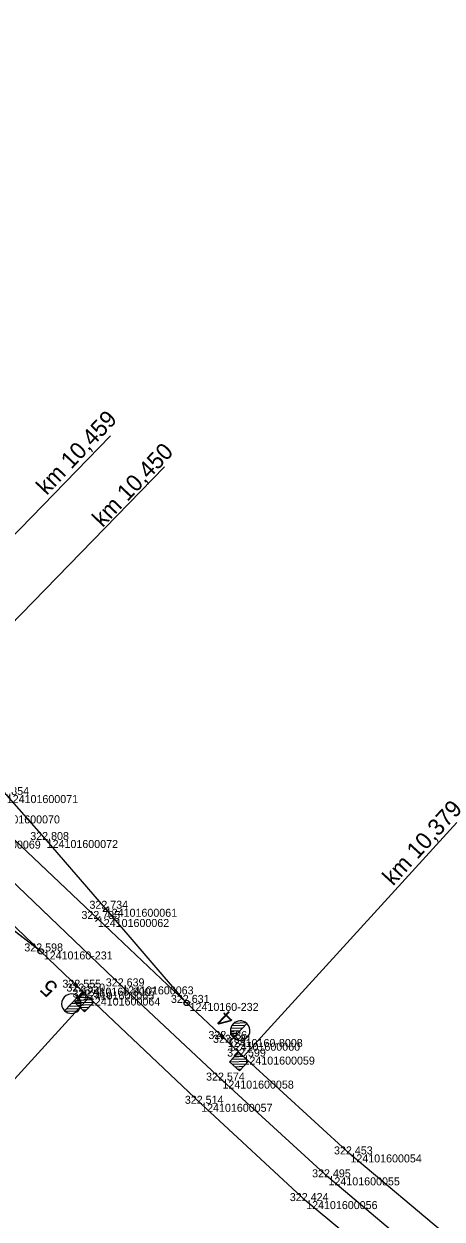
# Model space of a CAD drawing. Extents: x -616949 to -607976, y -1164436 to -1159224.
# Drawn here: x -616226.9 to -616164.1, y -1159749.3 to -1159570.1 of the extents above; entities that cross this region are included whole.
import ezdxf

# ---------------------------------------------------------------- set-up
doc = ezdxf.new("R2010")
doc.units = 0
for name, color, linetype in [('Vrstva 1', 7, 'Continuous'), ('Vrstva 2', 7, 'Continuous'), ('Vrstva 3', 7, 'Continuous'), ('Vrstva 60', 7, 'Continuous'), ('Vrstva 61', 7, 'Continuous')]:
    doc.layers.add(name, color=color, linetype=linetype)

msp = doc.modelspace()

# ---------------------------------------------------------------- linework, layer by layer
at = {"layer": 'Vrstva 1'}
for points in [[(-616196.14, -1159722.89), (-616196.73, -1159722.32), (-616202.46, -1159716.91), (-616215.79, -1159704.32), (-616232.19, -1159688.78), (-616245.9, -1159675.68), (-616250.85, -1159670.95), (-616252.01, -1159669.85), (-616262.33, -1159660.01), (-616274.66, -1159648.21), (-616291.39, -1159632.22), (-616312.18, -1159612.35), (-616313.6, -1159610.97), (-616321.94, -1159603.01), (-616323.38, -1159601.63), (-616330.7, -1159594.64), (-616332.15, -1159593.27), (-616353.46, -1159572.9), (-616354.89, -1159571.54), (-616372.69, -1159554.54)], [(-616218.05, -1159715.21), (-616218.66, -1159714.63), (-616224.36, -1159709.19), (-616237.66, -1159696.51), (-616252.73, -1159682.15), (-616263.69, -1159671.68), (-616264.9, -1159670.55), (-616281.06, -1159655.11), (-616297.26, -1159639.59), (-616319.41, -1159618.4), (-616337.57, -1159601.02), (-616360.84, -1159578.72), (-616379.28, -1159561.06)], [(-616196.14, -1159722.89), (-616196.73, -1159722.32), (-616202.46, -1159716.91), (-616214.6, -1159702.79), (-616223.47, -1159692.48), (-616229.46, -1159685.74), (-616241.59, -1159673.27), (-616259.02, -1159656.6), (-616271.36, -1159644.82), (-616287.75, -1159629.14), (-616308.99, -1159608.84), (-616310.74, -1159607.16), (-616318.53, -1159599.72), (-616320.21, -1159598.1), (-616327.35, -1159591.27), (-616329.08, -1159589.6), (-616351, -1159568.64)], [(-616166.13, -1159755.81), (-616181.17, -1159743.07), (-616197.09, -1159728.56), (-616212.13, -1159714.43), (-616235.07, -1159692.57), (-616248.23, -1159679.98), (-616265.42, -1159663.57), (-616277.85, -1159651.72), (-616294.35, -1159635.93), (-616315.47, -1159615.78), (-616316.9, -1159614.42), (-616325.14, -1159606.55), (-616326.55, -1159605.19), (-616333.88, -1159598.19), (-616335.34, -1159596.8), (-616356.93, -1159576.13)], [(-616218.05, -1159715.21), (-616218.66, -1159714.63), (-616224.36, -1159709.19), (-616239.15, -1159697.79)], [(-615908.84, -1159889.93), (-615910.27, -1159889.25), (-615923.84, -1159882.78), (-615939.55, -1159877.3), (-615950.02, -1159873.65), (-615958.35, -1159870.6), (-615972.88, -1159864.59), (-615984.54, -1159859.14), (-616001.22, -1159851.17), (-616023, -1159840.76), (-616044.09, -1159830.68), (-616066.72, -1159819.87), (-616088.67, -1159809.39), (-616107.11, -1159800.11), (-616112.99, -1159796.93), (-616128.47, -1159787.95), (-616137.63, -1159782.18), (-616142.77, -1159778.79), (-616153.3, -1159771.43), (-616169.07, -1159759.51), (-616184.52, -1159746.63), (-616200.28, -1159732.04), (-616217.13, -1159716.1), (-616218.05, -1159715.21)], [(-615938.86, -1159875.61), (-615940.27, -1159874.93), (-615953.84, -1159868.46), (-615968.03, -1159859.68), (-615983.58, -1159849.96), (-615996.64, -1159842.51), (-616003.45, -1159838.94), (-616018.15, -1159831.94), (-616039.7, -1159822.03), (-616063.66, -1159811.08), (-616084.21, -1159801.41), (-616107.46, -1159789.34), (-616114.32, -1159785.46), (-616128.35, -1159776.94), (-616131.48, -1159774.93), (-616137.2, -1159771.16), (-616148.09, -1159763.54), (-616163.09, -1159752.06), (-616177.88, -1159739.63), (-616193.93, -1159724.96), (-616196.14, -1159722.89)]]:
    msp.add_lwpolyline(points, dxfattribs=at)
at = {"layer": 'Vrstva 2'}
for p, q in [((-616224.36, -1159709.19), (-616239.15, -1159697.79)), ((-616214.21, -1159702.48), (-616214.99, -1159703.1)), ((-616215.45, -1159703.95), (-616216.13, -1159704.68)), ((-616202.46, -1159716.91), (-616214.6, -1159702.79)), ((-616218.76, -1159715.97), (-616220.78, -1159718.09)), ((-616218.36, -1159716.64), (-616219.42, -1159716.67)), ((-616218.53, -1159716.26), (-616219.05, -1159716.28)), ((-616218.76, -1159715.97), (-616218.05, -1159715.21)), ((-616218.85, -1159718.17), (-616220.62, -1159718.22)), ((-616218.51, -1159717.78), (-616220.53, -1159717.84)), ((-616218.35, -1159717.4), (-616220.16, -1159717.45)), ((-616218.31, -1159717.02), (-616219.79, -1159717.06)), ((-616195.68, -1159720.32), (-616193.67, -1159720.26)), ((-616195.43, -1159722.13), (-616193.42, -1159720)), ((-616195.35, -1159719.93), (-616193.58, -1159719.87)), ((-616195.43, -1159722.13), (-616196.14, -1159722.89)), ((-616195.88, -1159721.08), (-616194.4, -1159721.04)), ((-616195.84, -1159720.7), (-616194.03, -1159720.65)), ((-616195.83, -1159721.46), (-616194.77, -1159721.43)), ((-616195.66, -1159721.84), (-616195.14, -1159721.82))]:
    msp.add_line(p, q, dxfattribs=at)
for points in [[(-616218.05, -1159715.21), (-616218.66, -1159714.63), (-616224.36, -1159709.19), (-616237.66, -1159696.51)], [(-616196.14, -1159722.89), (-616196.73, -1159722.32), (-616202.46, -1159716.91), (-616215.79, -1159704.32)], [(-616219.54, -1159714.15), (-616218.66, -1159714.63), (-616219.18, -1159713.78)], [(-616197.61, -1159721.85), (-616196.73, -1159722.32), (-616197.26, -1159721.47)]]:
    msp.add_lwpolyline(points, dxfattribs=at)
for centre in [(-616224.36, -1159709.19), (-616202.46, -1159716.91)]:
    msp.add_circle(centre, 0.4, dxfattribs=at)
for centre, start, end in [((-616219.77, -1159717.03), 46.3462, 226.8158), ((-616219.77, -1159717.03), 226.6006, 46.5614), ((-616194.42, -1159721.06), 46.7577, 226.7186), ((-616194.42, -1159721.07), 226.5034, 46.9729)]:
    msp.add_arc(centre, 1.46, start, end, dxfattribs=at)
at = {"layer": 'Vrstva 3'}
for p, q in [((-616251.43, -1159670.4), (-616213.9, -1159631.89)), ((-616241.59, -1159673.27), (-616205.79, -1159636.51)), ((-616193.93, -1159724.96), (-616161.93, -1159689.86)), ((-616217.13, -1159716.1), (-616262.93, -1159766.19)), ((-616219.23, -1159716.86), (-616216.4, -1159716.78)), ((-616218.87, -1159716.48), (-616216.79, -1159716.42)), ((-616218.5, -1159716.09), (-616217.17, -1159716.05)), ((-616218.14, -1159715.71), (-616217.56, -1159715.69)), ((-616218.85, -1159717.23), (-616216.77, -1159717.17)), ((-616218.46, -1159717.59), (-616217.13, -1159717.55)), ((-616218.08, -1159717.95), (-616217.5, -1159717.94)), ((-616196.02, -1159725.76), (-616193.19, -1159725.64)), ((-616195.66, -1159725.37), (-616193.58, -1159725.28)), ((-616195.3, -1159724.98), (-616193.98, -1159724.92)), ((-616194.95, -1159724.59), (-616194.37, -1159724.56)), ((-616195.63, -1159726.12), (-616193.55, -1159726.03)), ((-616195.24, -1159726.48), (-616193.91, -1159726.42)), ((-616194.84, -1159726.84), (-616194.27, -1159726.81))]:
    msp.add_line(p, q, dxfattribs=at)
for points in [[(-616217.86, -1159715.41), (-616216.4, -1159716.78), (-616217.78, -1159718.24), (-616219.23, -1159716.86)], [(-616194.67, -1159724.29), (-616193.19, -1159725.64), (-616194.54, -1159727.11), (-616196.02, -1159725.76)]]:
    msp.add_lwpolyline(points, close=True, dxfattribs=at)
at = {"layer": 'Vrstva 60'}
for p, q in [((-616223.47, -1159692.48), (-616223.47, -1159692.48)), ((-616215.79, -1159704.32), (-616215.79, -1159704.32)), ((-616214.6, -1159702.79), (-616214.6, -1159702.79)), ((-616224.36, -1159709.19), (-616224.36, -1159709.19)), ((-616218.66, -1159714.63), (-616218.66, -1159714.63)), ((-616212.13, -1159714.43), (-616212.13, -1159714.43)), ((-616218.05, -1159715.21), (-616218.05, -1159715.21)), ((-616217.13, -1159716.1), (-616217.13, -1159716.1)), ((-616202.46, -1159716.91), (-616202.46, -1159716.91)), ((-616196.73, -1159722.32), (-616196.73, -1159722.32)), ((-616196.14, -1159722.89), (-616196.14, -1159722.89)), ((-616193.93, -1159724.96), (-616193.93, -1159724.96)), ((-616197.09, -1159728.56), (-616197.09, -1159728.56)), ((-616200.28, -1159732.04), (-616200.28, -1159732.04)), ((-616177.88, -1159739.63), (-616177.88, -1159739.63)), ((-616181.17, -1159743.07), (-616181.17, -1159743.07)), ((-616184.52, -1159746.63), (-616184.52, -1159746.63))]:
    msp.add_line(p, q, dxfattribs=at)

# ---------------------------------------------------------------- texts
at = {"layer": 'Vrstva 2'}
for s, rotation, p in [('5', 136.581, (-616221.61, -1159714.45)), ('4', 136.7381, (-616195.14, -1159719.12))]:
    msp.add_text(s, height=2.5, rotation=rotation, dxfattribs=at).set_placement(p)
at = {"layer": 'Vrstva 3'}
for s, rotation, p in [('km 10,459', 46.6221, (-616223.47, -1159640.88)), ('km 10,450', 46.2937, (-616215.08, -1159645.7)), ('km 10,379', 47.5726, (-616171.47, -1159699.46))]:
    msp.add_text(s, height=2.5, rotation=rotation, dxfattribs=at).set_placement(p)
at = {"layer": 'Vrstva 60'}
for s, p in [('124101600071', (-616229.46, -1159686.94)), ('124101600070', (-616232.19, -1159689.99)), ('124101600069', (-616235.07, -1159693.77)), ('124101600072', (-616223.47, -1159693.68)), ('124101600062', (-616215.79, -1159705.52)), ('124101600061', (-616214.6, -1159703.99)), (' 12410160-231', (-616224.36, -1159710.39)), (' 12410160-8007', (-616218.66, -1159715.83)), ('124101600065', (-616218.05, -1159716.41)), ('124101600063', (-616212.13, -1159715.63)), ('124101600064', (-616217.13, -1159717.3)), (' 12410160-232', (-616202.46, -1159718.11)), (' 12410160-8008', (-616196.73, -1159723.52)), ('124101600060', (-616196.14, -1159724.08)), ('124101600059', (-616193.93, -1159726.16)), ('124101600058', (-616197.09, -1159729.76)), ('124101600057', (-616200.28, -1159733.24)), ('124101600054', (-616177.88, -1159740.83)), ('124101600055', (-616181.17, -1159744.27)), ('124101600056', (-616184.52, -1159747.83))]:
    msp.add_text(s, height=1.2, dxfattribs=at).set_placement(p)
at = {"layer": 'Vrstva 61'}
for s, p in [('322.854', (-616231.91, -1159685.74)), ('322.808', (-616225.93, -1159692.48)), ('322.734', (-616217.05, -1159702.79)), ('322.735', (-616218.25, -1159704.32)), ('322.598', (-616226.82, -1159709.19)), ('322.555', (-616221.11, -1159714.63)), ('322.639', (-616214.59, -1159714.43)), ('322.550', (-616220.5, -1159715.21)), ('322.565', (-616219.59, -1159716.1)), ('322.631', (-616204.82, -1159716.91)), ('322.586', (-616199.19, -1159722.32)), ('322.581', (-616198.5, -1159722.89)), ('322.599', (-616196.38, -1159724.96)), ('322.574', (-616199.54, -1159728.56)), ('322.514', (-616202.73, -1159732.04)), ('322.453', (-616180.34, -1159739.63)), ('322.495', (-616183.63, -1159743.07)), ('322.424', (-616186.97, -1159746.63))]:
    msp.add_text(s, height=1.2, dxfattribs=at).set_placement(p)

doc.saveas('drawing.dxf')
